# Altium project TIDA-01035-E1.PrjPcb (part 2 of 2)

## Sheet TIDA-01035_ADC1.SchDoc
size 431 x 279 mm; Date: Not shown in title block; ApprovedBy: Not shown in title block; CheckedBy: Not shown in title block; Author: Not shown in title block; CompanyName: Not shown in title block; Engineer: Not shown in title block; Organization: Not shown in title block; Address1: Not shown in title block; Address2: Not shown in title block; Address3: Not shown in title block; Address4: Not shown in title block; DocumentNumber: 1; Revision: Use project parameter SCH_Rev; SheetNumber: 5; SheetTotal: 6; PageSetup: Record=PageOptions¦CenterHorizontal=True¦CenterVertical=True¦PrintScale=0.64¦XCorrection=1.00¦YCorrection=1.00¦PrintKind=0¦BorderSize=5000000¦LeftOffset=0¦BottomOffset=0¦Orientation=2¦PaperLength=1000¦PaperWidth=1000¦Scale=100¦PaperSource=15¦PrintQuality=600¦MediaType=1¦DitherType=10¦PrintScaleMode=1¦PaperKind=Letter¦PaperIndex=1
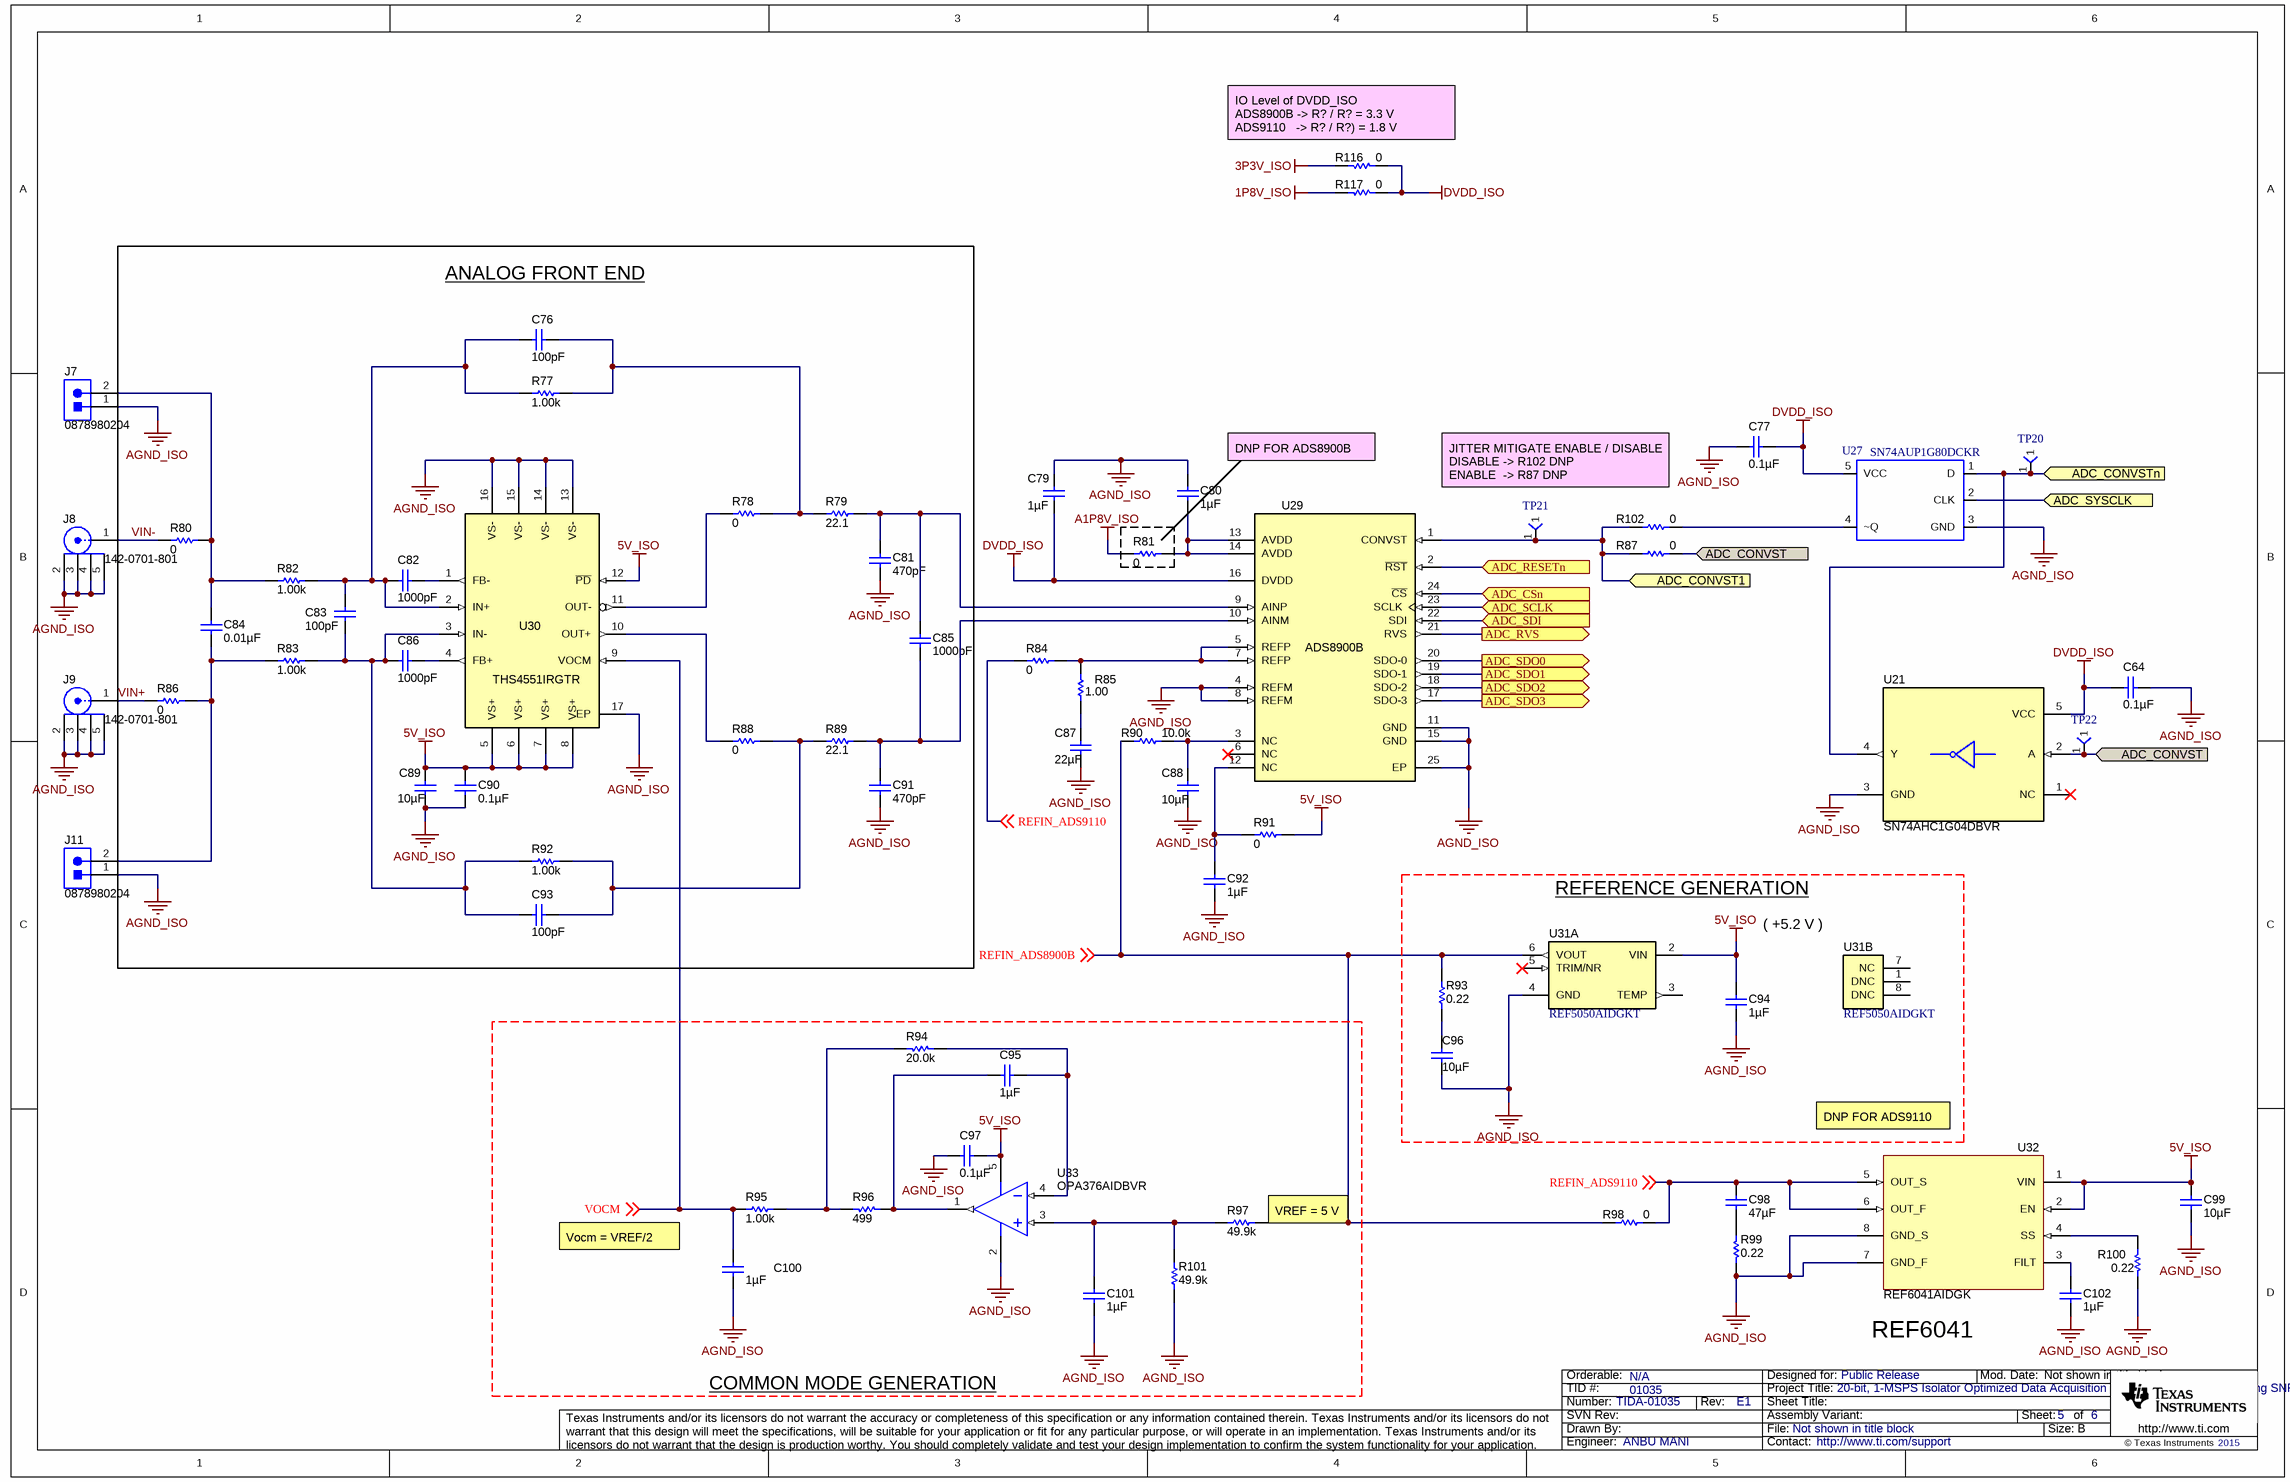
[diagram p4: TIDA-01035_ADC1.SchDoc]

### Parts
C64  ValueDisplayed: 0.1µF  [0402]  (hidden comment: GRM155R71C104KA88D)
C76  ValueDisplayed: 100pF  [0402]  (hidden comment: 885012005061)
C77  ValueDisplayed: 0.1µF  [0402]  (hidden comment: GRM155R71C104KA88D)
C79  ValueDisplayed: 1µF  [0603]  (hidden comment: GRM188R71E105KA12D)
C80  ValueDisplayed: 1µF  [0603]  (hidden comment: GRM188R71E105KA12D)
C81  ValueDisplayed: 470pF  [0805_HV]  (hidden comment: GRM2165C2A471JA01D)
C82  ValueDisplayed: 1000pF  [0603]  (hidden comment: GRM1885C1H102FA01J)
C83  ValueDisplayed: 100pF  [0402]  (hidden comment: 885012005061)
C84  ValueDisplayed: 0.01µF  [0805_HV]  (hidden comment: C0805C103F1GACTU)
C85  ValueDisplayed: 1000pF  [0805_HV]  (hidden comment: C0805C102J1GACTU)
C86  ValueDisplayed: 1000pF  [0603]  (hidden comment: GRM1885C1H102FA01J)
C87  ValueDisplayed: 22µF  [0603]  (hidden comment: GRM188R60J226MEA0J)
C88  ValueDisplayed: 10µF  [0805_HV]  (hidden comment: GRM21BR71A106KE51L)
C89  ValueDisplayed: 10µF  [0603_120]  (hidden comment: ZRB18AD71A106KE01L)
C90  ValueDisplayed: 0.1µF  [0402]  (hidden comment: GRM155R71C104KA88D)
C91  ValueDisplayed: 470pF  [0805_HV]  (hidden comment: GRM2165C2A471JA01D)
C92  ValueDisplayed: 1µF  [0603]  (hidden comment: GRM188R71E105KA12D)
C93  ValueDisplayed: 100pF  [0402]  (hidden comment: 885012005061)
C94  ValueDisplayed: 1µF  [0603]  (hidden comment: GRM188R71E105KA12D)
C95  ValueDisplayed: 1µF  [0603]  (hidden comment: GRM188R71E105KA12D)
C96  ValueDisplayed: 10µF  [0805_HV]  (hidden comment: GRM21BR71A106KE51L)
C97  ValueDisplayed: 0.1µF  [0603]  (hidden comment: C0603C104J3RACTU)
C98  ValueDisplayed: 47µF  [1210]  (hidden comment: GRM32ER71A476KE15L)
C99  ValueDisplayed: 10µF  [0805]  (hidden comment: GRM21BR71A106KE51L)
C100  ValueDisplayed: 1µF  [0603]  (hidden comment: GRM188R71E105KA12D)
C101  ValueDisplayed: 1µF  [0603]  (hidden comment: GRM188R71E105KA12D)
C102  ValueDisplayed: 1µF  [0603]  (hidden comment: GRM188R71A105KA61D)
J7  0878980204  [Molex_87898-0204]
J8  142-0701-801  [JOHNSON_142-0701-801]
J9  142-0701-801  [JOHNSON_142-0701-801]
J11  0878980204  [Molex_87898-0204]
R77  ValueDisplayed: 1.00k  [0603]  (hidden comment: RG1608P-102-B-T5)
R78  ValueDisplayed: 0  [0603]  (hidden comment: CRCW06030000Z0EA)
R79  ValueDisplayed: 22.1  [0603]  (hidden comment: RR0816Q-22R1-D-34R)
R80  ValueDisplayed: 0  [0603]  (hidden comment: ERJ-3GEY0R00V)
R81  ValueDisplayed: 0  [0402]  (hidden comment: ERJ-2GE0R00X)
R82  ValueDisplayed: 1.00k  [0603]  (hidden comment: RG1608P-102-B-T5)
R83  ValueDisplayed: 1.00k  [0603]  (hidden comment: RG1608P-102-B-T5)
R84  ValueDisplayed: 0  [0603]  (hidden comment: CRCW06030000Z0EA)
R85  ValueDisplayed: 1.00  [0603]  (hidden comment: CRCW06031R00FKEA)
R86  ValueDisplayed: 0  [0603]  (hidden comment: ERJ-3GEY0R00V)
R87  ValueDisplayed: 0  [0402]  (hidden comment: ERJ-2GE0R00X)
R88  ValueDisplayed: 0  [0603]  (hidden comment: CRCW06030000Z0EA)
R89  ValueDisplayed: 22.1  [0603]  (hidden comment: RR0816Q-22R1-D-34R)
R90  ValueDisplayed: 10.0k  [0402]  (hidden comment: ERJ-2RKF1002X)
R91  ValueDisplayed: 0  [0402]  (hidden comment: ERJ-2GE0R00X)
R92  ValueDisplayed: 1.00k  [0603]  (hidden comment: RG1608P-102-B-T5)
R93  ValueDisplayed: 0.22  [0402]  (hidden comment: ERJ-2BQFR22X)
R94  ValueDisplayed: 20.0k  [0603]  (hidden comment: RG1608P-203-B-T5)
R95  ValueDisplayed: 1.00k  [0603]  (hidden comment: CRCW06031K00FKEA)
R96  ValueDisplayed: 499  [0603]  (hidden comment: RG1608P-4990-B-T5)
R97  ValueDisplayed: 49.9k  [0603]  (hidden comment: RG1608P-4992-B-T5)
R98  ValueDisplayed: 0  [0603]  (hidden comment: CRCW06030000Z0EA)
R99  value 0.22  [0603]  (hidden comment: ERJ-3RQFR22V)
R100  value 0.22  [0603]  (hidden comment: ERJ-3RQFR22V)
R101  ValueDisplayed: 49.9k  [0603]  (hidden comment: RG1608P-4992-B-T5)
R102  ValueDisplayed: 0  [0402]  (hidden comment: ERJ-2GE0R00X)
R116  ValueDisplayed: 0  [0805_HV]  (hidden comment: CRCW08050000Z0EA)
R117  ValueDisplayed: 0  [0805_HV]  (hidden comment: CRCW08050000Z0EA)
TP20  TP-025-SMT  [TP_25MIL-SMT]  (value not drawn)
TP21  TP-025-SMT  [TP_25MIL-SMT]  (value not drawn)
TP22  TP-025-SMT  [TP_25MIL-SMT]  (value not drawn)
U21  SN74AHC1G04DBVR  [DBV0005A_N]
U27  SN74AUP1G80DCKR  [DCK0005A_N]
U29  ADS8900BIRGER  [RGE0024H]  (value not drawn)
U30  THS4551IRGTR  [RGT0016A]
U31  REF5050AIDGKT  [DGK0008A_N]  (parts A,B of 2)
U32  REF6041AIDGK  [DGK0008A_N]
U33  OPA376AIDBVR  [DBV0005A_N]

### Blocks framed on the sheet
REFERENCE GENERATION: C94 C96 R93 U31
COMMON MODE GENERATION: C95 C97 C100 C101 R94-R97 R101 U33

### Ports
ADC_CONVST1 (in), ADC_CONVST (in), ADC_CONVSTn (in), ADC_CSn (in), ADC_RESETn (in), ADC_RVS (out), ADC_SCLK (in), ADC_SDI (in), ADC_SDO0 (out), ADC_SDO1 (out), ADC_SDO2 (out), ADC_SDO3 (out), ADC_SYSCLK (in)

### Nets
1P8V_ISO: R117.2
3P3V_ISO: R116.2
5V_ISO: C89.1 C90.2 C94.1 C97.2 C99.2 R91.2 U30.5(VS+) U30.6(VS+) U30.7(VS+) U30.8(VS+) U30.12(~{PD}) U31.2(VIN) U32.1(VIN) U32.2(EN) U33.5(V+)
A1P8V_ISO: R81.1
AGND_ISO: C64.1 C77.1 C79.1 C80.2 C81.2 C87.2 C88.2 C89.2 C90.1 C91.2 C92.2 C94.2 C96.2 C97.1 C99.1 C100.2 C101.2 C102.2 J7.1 J8.2 J8.3 J8.4 J8.5 J9.2 J9.3 J9.4 J9.5 J11.1 R99.2 R100.1 R101.1 U21.3(GND) U27.3(GND) U29.4(REFM) U29.8(REFM) U29.11(GND) U29.15(GND) U29.25(EP) U30.13(VS-) U30.14(VS-) U30.15(VS-) U30.16(VS-) U30.17(EP) U31.4(GND) U32.7(GND_F) U32.8(GND_S) U33.2(V-)
DVDD_ISO: C64.2 C77.2 C79.2 R116.1 R117.1 U21.5(VCC) U27.5(VCC) U29.16(DVDD)
ADC_CONVST: R87.2 TP22.1 U21.2(A) ; port ADC_CONVST
ADC_CONVST1: R87.1 R102.1 TP21.1 U29.1(CONVST) ; port ADC_CONVST1
ADC_CONVSTn: TP20.1 U21.4(Y) U27.1(D) ; port ADC_CONVSTn
ADC_CSn: U29.24(~{CS}) ; port ADC_CSn
ADC_RESETn: U29.2(~{RST}) ; port ADC_RESETn
ADC_RVS: U29.21(RVS) ; port ADC_RVS
ADC_SCLK: U29.23(SCLK) ; port ADC_SCLK
ADC_SDI: U29.22(SDI) ; port ADC_SDI
ADC_SDO0: U29.20(SDO-0) ; port ADC_SDO0
ADC_SDO1: U29.19(SDO-1) ; port ADC_SDO1
ADC_SDO2: U29.18(SDO-2) ; port ADC_SDO2
ADC_SDO3: U29.17(SDO-3) ; port ADC_SDO3
ADC_SYSCLK: U27.2(CLK) ; port ADC_SYSCLK
REFIN_ADS8900B: R90.1 R93.2 R97.2 R98.1 U31.6(VOUT) ; off-sheet REFIN_ADS8900B
REFIN_ADS9110: C98.2 R84.2 R98.2 U32.5(OUT_S) U32.6(OUT_F) ; off-sheet REFIN_ADS9110
VIN+: J9.1 R86.1
VIN-: J8.1 R80.1
VOCM: C100.1 R95.1 U30.9(VOCM) ; off-sheet VOCM
NetC76_1: C76.1 R77.2 R78.2 R79.1
NetC76_2: C76.2 C82.2 C83.1 R77.1 R82.2 U30.2(IN+)
NetC80_1: C80.1 R81.2 U29.13(AVDD) U29.14(AVDD)
NetC81_1: C81.1 C85.1 R79.2 U29.9(AINP)
NetC82_1: C82.1 U30.1(FB-)
NetC83_2: C83.2 C86.2 C93.2 R83.2 R92.1 U30.3(IN-)
NetC84_1: C84.1 J11.2 R83.1 R86.2
NetC84_2: C84.2 J7.2 R80.2 R82.1
NetC85_2: C85.2 C91.1 R89.2 U29.10(AINM)
NetC86_1: C86.1 U30.4(FB+)
NetC87_1: C87.1 R85.1
NetC88_1: C88.1 R90.2 U29.3(NC)
NetC92_1: C92.1 R91.1 U29.12(NC)
NetC93_1: C93.1 R88.2 R89.1 R92.2
NetC95_1: C95.1 R96.1 U33.1(OUT)
NetC95_2: C95.2 R94.1 U33.4(IN-)
NetC96_1: C96.1 R93.1
NetC98_1: C98.1 R99.1
NetC101_1: C101.1 R97.1 R101.2 U33.3(IN+)
NetC102_1: C102.1 U32.3(FILT)
NetR78_1: R78.1 U30.11(OUT-)
NetR84_1: R84.1 R85.2 U29.5(REFP) U29.7(REFP)
NetR88_1: R88.1 U30.10(OUT+)
NetR94_2: R94.2 R95.2 R96.2
NetR100_2: R100.2 U32.4(SS)
NetR102_2: R102.2 U27.4(~Q)

Not connected (* = marked no-connect by the designer): U21 1(NC)*; U29 6(NC)*; U31 1(DNC) 3(TEMP) 5(TRIM/NR)* 7(NC) 8(DNC)

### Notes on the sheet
- (near R116) IO Level of DVDD_ISO
  ADS8900B -> R? / R? = 3.3 V
  ADS9110   -> R? / R?) = 1.8 V
- ANALOG FRONT END
- (near C80) DNP FOR ADS8900B
- JITTER MITIGATE ENABLE / DISABLE
  DISABLE -> R102 DNP
  ENABLE  -> R87 DNP
- (near U29) ADS8900B
- (near R93) ( +5.0 V )
- ( +5.2 V )
- DNP FOR ADS9110
- (near R97) VREF = 5 V
- Vocm = VREF/2
- REF6041

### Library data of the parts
C64 C77 C90 = GRM155R71C104KA88D: CAP, CERM, 0.1 µF, 16 V, +/- 10%, X7R, 0402; Manufacturer: MuRata; Polarized: N; CompType: Capacitor; Value: 0.1uF; U/M: EA; Cap_F: 0.0000001; Tolerance_%: 10; Value1: Unknown; VDC_V: 16; Value2: 16V; TaMin_C: -55; TaMax_C: 125
C76 C83 C93 = 885012005061: CAP, CERM, 100 pF, 50 V, +/- 5%, C0G/NP0, 0402; Manufacturer: Wurth Elektronik; Polarized: N; CompType: Capacitor; Value: 100pF; U/M: EA; Cap_F: 0.0000000001; Tolerance_%: 5; Value1: Unknown; VDC_V: 50; Value2: 50V; TaMin_C: -55; TaMax_C: 125; AEC Category: Q200
C79 C80 C94 = GRM188R71E105KA12D: CAP, CERM, 1 µF, 25 V, +/- 10%, X7R, 0603; Manufacturer: MuRata; Polarized: N; CompType: Capacitor; Value: 1uF; U/M: EA; Cap_F: 0.000001; Tolerance_%: 10; Value1: Unknown; VDC_V: 25; Value2: 25V; TaMin_C: -55; TaMax_C: 125
C81 C91 = GRM2165C2A471JA01D: CAP, CERM, 470 pF, 100 V, +/- 5%, C0G/NP0, 0805; Manufacturer: MuRata; Polarized: N; CompType: Capacitor; Value: 470pF; U/M: EA; Cap_F: 0.00000000047; Tolerance_%: 5; Value1: Unknown; VDC_V: 100; Value2: 100V; TaMin_C: -55; TaMax_C: 125; Cap_Case: 0805; SizeArea_mm2: 2.5; SizeAreaWB_mm2: 6.75; SizeX_mm: 2; SizeY_mm: 1.25; SizeZ_mm: 1.45; AEC Category: Q200
C82 C86 = GRM1885C1H102FA01J: CAP, CERM, 1000 pF, 50 V, +/- 1%, C0G/NP0, 0603; Manufacturer: MuRata; Polarized: N; CompType: Capacitor; Value: 1000pF; U/M: EA; Cap_F: 0.000000001; Tolerance_%: 1; Value1: Unknown; VDC_V: 50; Value2: 50V; TaMin_C: -55; TaMax_C: 125; AEC Category: Q200; SizeArea_mm2: 1.28; SizeAreaWB_mm2: 4.68; SizeX_mm: 1.6; SizeY_mm: 0.8
C84 = C0805C103F1GACTU: CAP, CERM, 0.01 µF, 100 V, +/- 1%, C0G/NP0, 0805; Manufacturer: Kemet; Polarized: N; CompType: Capacitor; Value: 0.01uF; U/M: EA; Cap_F: 0.00000001; Tolerance_%: 1; Value1: Unknown; VDC_V: 100; Value2: 100V; TaMin_C: -55; TaMax_C: 125; Cap_Case: 0805; AEC Category: Q200
C85 = C0805C102J1GACTU: CAP, CERM, 1000 pF, 100 V, +/- 5%, C0G/NP0, 0805; Manufacturer: Kemet; Polarized: N; CompType: Capacitor; Value: 1000pF; U/M: EA; Cap_F: 0.000000001; Tolerance_%: 5; ESR_ohm: 0.025; Value1: 0.025 ohm; VDC_V: 100; Value2: 100V; IRMS_A: 1.71; TaMin_C: -55; TaMax_C: 125; Cap_Case: 0805; SizeArea_mm2: 2.5; SizeAreaWB_mm2: 6.75; SizeX_mm: 2; SizeY_mm: 1.25; SizeZ_mm: 1.45; AEC Category: Q200
C87 = GRM188R60J226MEA0J: CAP, CERM, 22 µF, 6.3 V, +/- 20%, X5R, 0603; Manufacturer: MuRata; Polarized: N; CompType: Capacitor; Value: 22uF; U/M: EA; Cap_F: 0.000022; Tolerance_%: 20; Value1: Unknown; VDC_V: 6.3; Value2: 6.3V; TaMin_C: -55; TaMax_C: 85; AEC Category: Q200
C88 C96 = GRM21BR71A106KE51L: CAP, CERM, 10 µF, 10 V, +/- 10%, X7R, 0805; Manufacturer: MuRata; Polarized: N; CompType: Capacitor; Value: 10uF; U/M: EA; Cap_F: 0.00001; Tolerance_%: 10; ESR_ohm: 0.003; Value1: 0.003 ohm; Value2: 10V; TaMin_C: -55; TaMax_C: 125; Cap_Case: 0805; AEC Category: Q200
C89 = ZRB18AD71A106KE01L: CAP, CERM, 10 µF, 10 V, +/- 10%, X7T, 0603; Manufacturer: MuRata; Polarized: N; CompType: Capacitor; Value: 10uF; U/M: EA; Cap_F: 0.00001; Tolerance_%: 10; Value1: Unknown; Value2: 10V; TaMin_C: -55; TaMax_C: 125; Cap_Case: 0603; AEC Category: Q200
C92 C95 C100 C101 = GRM188R71E105KA12D: CAP, CERM, 1 µF, 25 V, +/- 10%, X7R, 0603; Manufacturer: MuRata; Polarized: N; CompType: Capacitor; Value: 1uF; U/M: EA; Cap_F: 0.000001; Tolerance_%: 10; Value1: Unknown; VDC_V: 25; Value2: 25V; TaMin_C: -55; TaMax_C: 125; AEC Category: Q200
C97 = C0603C104J3RACTU: CAP, CERM, 0.1 µF, 25 V, +/- 5%, X7R, 0603; Manufacturer: Kemet; Polarized: N; CompType: Capacitor; Value: 0.1uF; U/M: EA; Cap_F: 0.0000001; Tolerance_%: 5; Value1: Unknown; VDC_V: 25; Value2: 25V; TaMin_C: -55; TaMax_C: 125; AEC Category: Q200
C98 = GRM32ER71A476KE15L: CAP, CERM, 47 µF, 10 V, +/- 10%, X7R, 1210; Manufacturer: MuRata; Polarized: N; CompType: Capacitor; Value: 47uF; U/M: EA; Cap_F: 0.000047; Tolerance_%: 10; Value1: Unknown; Value2: 10V; TaMin_C: -55; TaMax_C: 125
C99 = GRM21BR71A106KE51L: CAP, CERM, 10uF, 10V, +/-10%, X7R, 0805; Manufacturer: MuRata; Polarized: N; CompType: Capacitor; U/M: EA; Cap_F: 0.00001; Tolerance_%: 10; ESR_Ohm: 0.003; Value1: 0.003 ohm; TaMin_C: -55; TaMax_C: 125
C102 = GRM188R71A105KA61D: CAP, CERM, 1uF, 10V, +/-10%, X7R, 0603; Manufacturer: MuRata; Polarized: N; CompType: Capacitor; U/M: EA; Cap_F: 0.000001; Tolerance_%: 10; ESR_Ohm: 0.011; Value1: 0.011 ohm; TaMin_C: -55; TaMax_C: 125
J7 J11 = 87898-0204: Header, 2.54 mm, 2x1, Gold, R/A, SMT; Manufacturer: Molex; SymbolCreator: a0412235; U/M: EA
J8 J9 = 142-0701-801: Connector, End launch SMA, 50 ohm, SMT; Manufacturer: Johnson; SymbolCreator: X0208326; U/M: EA
R77 R82 R83 R92 = RG1608P-102-B-T5: RES, 1.00 k, 0.1%, 0.1 W, 0603; Manufacturer: Susumu Co Ltd; CompType: Resistor; Value: 1.00k; Res_ohm: 1000; Value_Code: 1k00; Tolerance_%: 0.1; Value2: 0.1W; VDC_V: 75; TempCo: 25 ppm/C; EIA_Code: E192; U/M: EA
R78 R88 = CRCW06030000Z0EA: RES, 0, 5%, 0.1 W, 0603; Manufacturer: Vishay-Dale; CompType: Resistor; Value: 0; Value_Code: 0000; Tolerance_%: 5; Power_W: 0.1; Value2: 0.1W; VDC_V: 75; TempCo: 200 ppm/C; EIA_Code: E24; U/M: EA; AEC Category: Q200; SizeArea_mm2: 1.28; SizeX_mm: 1.6; SizeY_mm: 0.8; SizeZ_mm: 1
R79 R89 = RT0603BRD0722R1L: RES SMD 22.1 OHM 0.5% 1/16W 0603; Manufacturer: Susumu; CompType: Resistor; Value: 22.1; Value_Code: 22R1; Tolerance_%: 0.1; Value1: 0.1%; Value2: 0.1W; VDC_V: 75; TempCo: 25 ppm/C; EIA_Code: E192; U/M: EA; SizeArea_mm2: 1.28; SizeX_mm: 1.6; SizeY_mm: 0.8; SizeZ_mm: 1; AEC Category: Q200
R80 R86 = ERJ-3GEY0R00V: RES, 0, 5%, 0.1 W, 0603; Manufacturer: Panasonic; CompType: Resistor; Value: 0; Value_Code: 0000; Tolerance_%: 5; Power_W: 0.1; Value2: 0.1W; VDC_V: 50; TempCo: 600 ppm/C; EIA_Code: E24; U/M: EA; AEC Category: Q200
R81 R87 R91 R102 = ERJ-2GE0R00X: RES, 0, 5%, 0.063 W, 0402; Manufacturer: Panasonic; CompType: Resistor; Value: 0; Value_Code: 0000; Tolerance_%: 5; Power_W: 0.063; Value2: 0.063W; VDC_V: 50; TempCo: 600 ppm/C; EIA_Code: E24; U/M: EA; AEC Category: Q200
R84 R98 = CRCW06030000Z0EA: RES, 0, 5%, 0.1 W, 0603; Manufacturer: Vishay-Dale; CompType: Resistor; Value: 0; Value_Code: 0000; Tolerance_%: 5; Power_W: 0.1; Value2: 0.1W; VDC_V: 75; TempCo: 200 ppm/C; EIA_Code: E24; U/M: EA; AEC Category: Q200
R85 = CRCW06031R00FKEA: RES, 1.00, 1%, 0.1 W, 0603; Manufacturer: Vishay-Dale; CompType: Resistor; Value: 1.00; Res_ohm: 1; Value_Code: 1R00; Power_W: 0.1; Value2: 0.1W; VDC_V: 75; TempCo: 100 ppm/C; EIA_Code: E96; U/M: EA; AEC Category: Q200
R90 = ERJ-2RKF1002X: RES, 10.0 k, 1%, 0.1 W, 0402; Manufacturer: Panasonic; CompType: Resistor; Value: 10.0k; Res_ohm: 10000; Value_Code: 10k0; Tolerance_%: 1; Power_W: 0.1; Value2: 0.1W; VDC_V: 50; TempCo: 100 ppm/C; EIA_Code: E96; U/M: EA; AEC Category: Q200
R93 = ERJ-2BQFR22X: RES, 0.22, 1%, 0.125 W, 0402; Manufacturer: Panasonic; CompType: Resistor; Value: 0.22; Value_Code: R220; Tolerance_%: 1; Power_W: 0.125; Value2: 0.125W; TempCo: 250 ppm/C; EIA_Code: E96; U/M: EA; AEC Category: Q200
R94 = RG1608P-203-B-T5: RES, 20.0 k, 0.1%, 0.1 W, 0603; Manufacturer: Susumu Co Ltd; CompType: Resistor; Value: 20.0k; Res_ohm: 20000; Value_Code: 20k0; Tolerance_%: 0.1; Value2: 0.1W; VDC_V: 75; TempCo: 25 ppm/C; EIA_Code: E192; U/M: EA; AEC Category: Q200
R95 = CRCW06031K00FKEA: RES, 1.00 k, 1%, 0.1 W, 0603; Manufacturer: Vishay-Dale; CompType: Resistor; Value: 1.00k; Res_ohm: 1000; Value_Code: 1k00; Tolerance_%: 1; Power_W: 0.1; Value2: 0.1W; VDC_V: 75; TempCo: 100 ppm/C; EIA_Code: E96; U/M: EA; AEC Category: Q200
R96 = RG1608P-4990-B-T5: RES, 499, 0.1%, 0.1 W, 0603; Manufacturer: Susumu Co Ltd; CompType: Resistor; Value: 499; Value_Code: 499R; Tolerance_%: 0.1; Value2: 0.1W; VDC_V: 75; TempCo: 25 ppm/C; EIA_Code: E192; U/M: EA; AEC Category: Q200
R97 R101 = RG1608P-4992-B-T5: RES, 49.9 k, 0.1%, 0.1 W, 0603; Manufacturer: Susumu Co Ltd; CompType: Resistor; Value: 49.9k; Res_ohm: 49900; Value_Code: 49k9; Tolerance_%: 0.1; Value2: 0.1W; VDC_V: 75; TempCo: 25 ppm/C; EIA_Code: E192; U/M: EA; AEC Category: Q200
R99 R100 = ERJ-3RQFR22V: RES, 0.22 ohm, 1%, 0.1W, 0603; Manufacturer: Panasonic; CompType: Resistor; Value_Code: R220; Tolerance_%: 1; Power_W: 0.1; TempCo: 300 ppm/C; EIA_Code: E96; U/M: EA
R116 R117 = CRCW08050000Z0EA: RES, 0, 5%, 0.125 W, 0805; Manufacturer: Vishay-Dale; CompType: Resistor; Value: 0; Value_Code: 0000; Tolerance_%: 5; Power_W: 0.125; Value2: 0.125W; VDC_V: 150; TempCo: 200 ppm/C; EIA_Code: E24; U/M: EA; AEC Category: Q200
TP20-TP22 = TP-025-SMT: Test Point, O.025"; Manufacturer: STD; Value: STD
U21 = SN74AHC1G04DBVR: SINGLE SCHMITT-TRIGGER INVERTER GATE, DBV0005A; Alternate PartNumber: SN74AHC1G04DBVT; Manufacturer: Texas Instruments; SymbolCreator: a0411947; CompType: IC; U/M: EA
U27 = SN74AUP1G80DCK: IC, Single Positive-Edge-Triggered D-Type Flip-Flop; Manufacturer: TI; Alternate Manufacturer: None; Area: 23200
U29 = ADS9110IRGER: 18-Bit, 2-MSPS, 20-mW, SAR ADC with Enhanced Serial Interface, RGE0024H; Alternate PartNumber: ADS9110IRGET; Manufacturer: Texas Instruments; SymbolCreator: Altium; CompType: IC; U/M: EA
U30 = THS4551IRGTR: Low Power, Precision, 160MHz, Fully Differential Amplifier, RGT0016A; Alternate PartNumber: THS4551IRGTT; Manufacturer: Texas Instruments; SymbolCreator: Altium; SizeX_mm: 4; SizeZ_mm: 1; CompType: IC; U/M: EA
U31 = REF5050AIDGKT: Low Noise, Very Low Drift, Precision Voltage Reference, -40 to 125 degC, 8-pin VSSOP (DGK), Green (RoHS & no Sb/Br); Manufacturer: Texas Instruments; Alternate PartNumber: Equivalent; Initial Accuracy @ 25/deg C(%): 0.05; Iout/Iz(Max)(mA): 10; Iq(Max)(uA): 1000; Rating: Catalog; SubFamily: Series Voltage Reference; Temp Coeff(Max)(ppm/ degree C): 3; VI(Max)(V): 18; VI(Min)(V): 5.2; VO(V): 5
U32 = REF6025AIDGK: High-Precision Voltage Reference with Integrated High-Bandwidth Buffer, DGK0008A; Manufacturer: Texas Instruments; SymbolCreator: Altium; CompType: IC; U/M: EA
U33 = OPA376AIDBVR: Precision, Low Noise, Low Iq Operational Amplifier, 2.2 to 5.5 V, -40 to 125 degC, 5-pin SOT23 (DBV0005A), Green (RoHS & no Sb/Br); Manufacturer: Texas Instruments; Alternate PartNumber: Equivalent; CMRR(Min)(dB): 76; IIB(Max)(pA): 10; Iq per channel(Max)(mA): 0.95; Number of Channels: 1; Offset Drift(Typ)(uV/C): 0.32; Slew Rate(Typ)(V/us): 2; Sub Family: Low Input Bias Current Amp (<=10pA), Low Noise Amp (<=10nV/rtHz), Low Offset Voltage Amplifier (<=500uV), Low Supply Voltage Amplifier (<=2.7V), Precision Amplifier; Total Supply Voltage(Max)(+5V is 5, +/-5V is 10): 5.5; Total Supply Voltage(Min)(+5V is 5, +/-5V is 10): 2.2; Vio (25C)(Max)(mV): 0.025; Vn at 1kHz(Typ)(nV/rtHz): 7.5

## Sheet TIDA-01035_Hardware.SchDoc
size 431 x 279 mm; Date: Not shown in title block; ApprovedBy: Not shown in title block; CheckedBy: Not shown in title block; Author: Not shown in title block; CompanyName: Not shown in title block; Engineer: Not shown in title block; Organization: Not shown in title block; Address1: Not shown in title block; Address2: Not shown in title block; Address3: Not shown in title block; Address4: Not shown in title block; DocumentNumber: 1; Revision: Use project parameter SCH_Rev; SheetNumber: 6; SheetTotal: 6; PageSetup: Record=PageOptions¦CenterHorizontal=True¦CenterVertical=True¦PrintScale=1.00¦XCorrection=1.00¦YCorrection=1.00¦PrintKind=0¦BorderSize=5000000¦LeftOffset=0¦BottomOffset=0¦Orientation=2¦PaperLength=1000¦PaperWidth=1000¦Scale=100¦PaperSource=15¦PrintQuality=600¦MediaType=1¦DitherType=10¦PaperKind=Letter¦PrintScaleMode=1
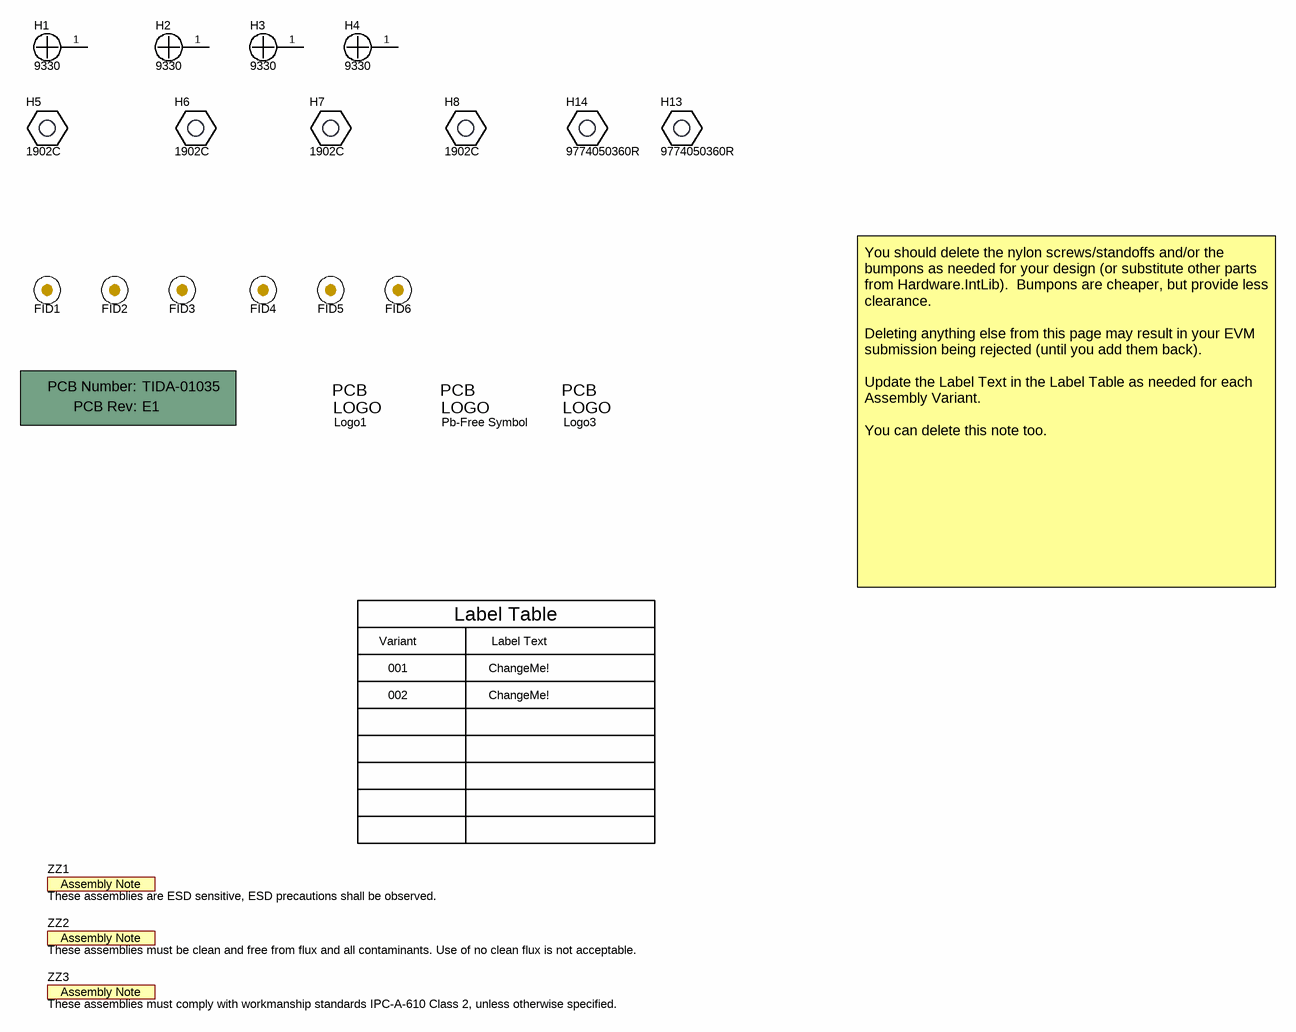
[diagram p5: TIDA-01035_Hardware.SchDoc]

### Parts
!PCB1  Printed Circuit Board  (value not drawn)  (mechanical)
FID1  Fiducial  [Fiducial10-20]  (value not drawn)
FID2  Fiducial  [Fiducial10-20]  (value not drawn)
FID3  Fiducial  [Fiducial10-20]  (value not drawn)
FID4  Fiducial  [Fiducial10-20]  (value not drawn)
FID5  Fiducial  [Fiducial10-20]  (value not drawn)
FID6  Fiducial  [Fiducial10-20]  (value not drawn)
H1  9330  [NY PMS 440 0025 PH]
H2  9330  [NY PMS 440 0025 PH]
H3  9330  [NY PMS 440 0025 PH]
H4  9330  [NY PMS 440 0025 PH]
H5  1902C  [Keystone_1902C]
H6  1902C  [Keystone_1902C]
H7  1902C  [Keystone_1902C]
H8  1902C  [Keystone_1902C]
H13  9774050360R  [Wurth_WA-SMSI]
H14  9774050360R  [Wurth_WA-SMSI]
Logo1  ESD Susceptible  [ESD_Overlay_small]  (value not drawn)  (no BOM)
Logo2  Pb-Free Symbol  [Pb-Free_Overlay_Small]  (no BOM)
Logo3  FCC disclaimer  [FCC_disclaimer]  (value not drawn)  (no BOM)
ZZ1  These assemblies are ESD sensitive, ESD precautions shall be observed.  [AssemblyNote]  (no BOM)
ZZ2  These assemblies must be clean and free from flux and all contaminants. Use of no clean flux is not acceptable.  [AssemblyNote]  (no BOM)
ZZ3  These assemblies must comply with workmanship standards IPC-A-610 Class 2, unless otherwise specified.  [AssemblyNote]  (no BOM)

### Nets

Not connected (* = marked no-connect by the designer): H1 1; H2 1; H3 1; H4 1

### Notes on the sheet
- Variant
- Label Table
- Label Text
- You should delete the nylon screws/standoffs and/or the bumpons as needed for your design (or substitute other parts from Hardware.IntLib).  Bumpons are cheaper, but provide less clearance.
  Deleting anything else from this page may result in your EVM submission being rejected (until you add them back).
  Update the Label Text in the Label Table as needed for each Assembly Variant.
  You can delete this note too.
- 001
- 002
- ChangeMe!

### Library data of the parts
!PCB1 = PCB: Manufacturer: Any; PartNumber: TIDA-01035; SymbolCreator: a0412235
FID1-FID6 = Fiducial: Fiducial mark.  There is nothing to buy or mount.; SymbolCreator: codlsc
H1-H4 = NY PMS 440 0025 PH: Machine Screw, Round, #4-40 x 1/4, Nylon, Philips panhead; Manufacturer: Keystone Electronics; CompType: Hardware; SymbolCreator: codlsc; U/M: EA
H5-H8 = 1902C: Standoff, Hex, 0.5"L #4-40 Nylon; Manufacturer: Keystone; CompType: Hardware
H13 H14 = 9774050360R: ROUND STANDOFF M3 STEEL 11MM; Manufacturer: Wurth Elektronik; SymbolCreator: a0412235
Logo1 = ESD_Susceptible: ESD Susceptible Symbol; SymbolCreator: a0412235
Logo2 = Pb-Free: SymbolCreator: a0412235
Logo3 = FCC_disclaimer: SymbolCreator: a0412235
ZZ1-ZZ3 = AssemblyNote: SymbolCreator: codlsc

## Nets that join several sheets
1P8V_ISO: TIDA-01035_CONNECTOR (C11.1 U3.5), TIDA-01035_POWER_ISOLATION (C38.1 C39.1 TP8.1 U9.5), TIDA-01035_ADC1 (R117.2)
3P3V: TIDA-01035_POWER_ISOLATION (5 pins), TIDA-01035_DATA_ISOLATION (12 pins)
3P3V_ISO: TIDA-01035_CONNECTOR (7 pins), TIDA-01035_POWER_ISOLATION (5 pins), TIDA-01035_DATA_ISOLATION (22 pins), TIDA-01035_ADC1 (R116.2)
5V_ISO: TIDA-01035_POWER_ISOLATION (5 pins), TIDA-01035_ADC1 (15 pins)
A1P8V_ISO: TIDA-01035_POWER_ISOLATION (C42.1 C43.1 TP9.1 U10.5), TIDA-01035_ADC1 (R81.1)
AGND_ISO: TIDA-01035_CONNECTOR (11 pins), TIDA-01035_POWER_ISOLATION (45 pins), TIDA-01035_DATA_ISOLATION (37 pins), TIDA-01035_ADC1 (47 pins)
DVDD_ISO: TIDA-01035_CONNECTOR (5 pins), TIDA-01035_DATA_ISOLATION (7 pins), TIDA-01035_ADC1 (8 pins)
GND: TIDA-01035_CONNECTOR (14 pins), TIDA-01035_POWER_ISOLATION (27 pins), TIDA-01035_DATA_ISOLATION (15 pins)
ADC_CONVST: TIDA-01035_DATA_ISOLATION (R62.2 U12.11), TIDA-01035_ADC1 (R87.2 TP22.1 U21.2)
ADC_CSn: TIDA-01035_DATA_ISOLATION (R68.2 U12.12), TIDA-01035_ADC1 (U29.24)
ADC_RESETn: TIDA-01035_DATA_ISOLATION (R57.2 U12.10), TIDA-01035_ADC1 (U29.2)
ADC_RVS: TIDA-01035_DATA_ISOLATION (R76.2 U13.11), TIDA-01035_ADC1 (U29.21)
ADC_SCLK: TIDA-01035_DATA_ISOLATION (R60.2 U12.13), TIDA-01035_ADC1 (U29.23)
ADC_SDI: TIDA-01035_DATA_ISOLATION (R67.2 U13.13), TIDA-01035_ADC1 (U29.22)
ADC_SDO0: TIDA-01035_DATA_ISOLATION (R66.2 U14.10), TIDA-01035_ADC1 (U29.20)
ADC_SDO1: TIDA-01035_DATA_ISOLATION (R58.2 U14.11), TIDA-01035_ADC1 (U29.19)
ADC_SDO2: TIDA-01035_DATA_ISOLATION (R61.2 U14.12), TIDA-01035_ADC1 (U29.18)
ADC_SDO3: TIDA-01035_DATA_ISOLATION (R63.2 U14.13), TIDA-01035_ADC1 (U29.17)
ADC_SYSCLK: TIDA-01035_CONNECTOR (R14.2 R17.2 TP1.1), TIDA-01035_DATA_ISOLATION (R71.2 U13.10), TIDA-01035_ADC1 (U27.2)
CONVST: TIDA-01035_CONNECTOR (R3.1), TIDA-01035_DATA_ISOLATION (U11.5)
CSn: TIDA-01035_CONNECTOR (R4.1), TIDA-01035_DATA_ISOLATION (U11.4)
ISO_SCL: TIDA-01035_CONNECTOR (J3.3 R16.1 U2.8), TIDA-01035_DATA_ISOLATION (R73.1 U25.6)
ISO_SDA: TIDA-01035_CONNECTOR (J3.2 R15.1 U2.7), TIDA-01035_DATA_ISOLATION (R75.1 U25.7)
NISO_SCL: TIDA-01035_CONNECTOR (J1.58 U1.6), TIDA-01035_DATA_ISOLATION (R74.1 U25.3)
NISO_SDA: TIDA-01035_CONNECTOR (J1.56 U1.5), TIDA-01035_DATA_ISOLATION (R72.1 U25.2)
RVS: TIDA-01035_CONNECTOR (R8.1), TIDA-01035_DATA_ISOLATION (U19.5)
SCLK: TIDA-01035_CONNECTOR (R5.1), TIDA-01035_DATA_ISOLATION (U11.3)
SDI: TIDA-01035_CONNECTOR (R2.1), TIDA-01035_DATA_ISOLATION (U19.4)
SDO0: TIDA-01035_CONNECTOR (R9.1), TIDA-01035_DATA_ISOLATION (U22.14)
SDO1: TIDA-01035_CONNECTOR (R10.1), TIDA-01035_DATA_ISOLATION (U22.13)
SDO2: TIDA-01035_CONNECTOR (R11.1), TIDA-01035_DATA_ISOLATION (U22.12)
SDO3: TIDA-01035_CONNECTOR (R12.1), TIDA-01035_DATA_ISOLATION (U22.11)
SRESETn: TIDA-01035_CONNECTOR (R1.1), TIDA-01035_DATA_ISOLATION (U11.6)
SYSCLK: TIDA-01035_CONNECTOR (R7.1), TIDA-01035_DATA_ISOLATION (U19.6)

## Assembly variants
ADS8900B: not fitted C6 C40 C41 C42 C43 C46 C47 C48 C49 C50 C51 C76 C83 C84 C93 C98 C99 C102 FID1 FID2 FID3 R13 R14 R18 R27 R28 R30 R32 R37 R41 R42 R43 R44 R45 R46 R49 R50 R51 R52 R81 R84 R87 R98 R99 R100 R103 R105 R106 R107 R108 R109 R110 R111 R112 R113 R114 R115 R117 T2 U10 U12 U13 U14 U32 Y1
ADS9110: not fitted C6 C76 C81 C83 C84 C88 C91 C92 C93 C96 FID1 FID2 FID3 R13 R17 R27 R28 R30 R32 R37 R41 R42 R43 R44 R45 R46 R49 R50 R51 R52 R57 R58 R60 R61 R62 R63 R66 R67 R68 R71 R76 R87 R90 R91 R93 R103 T2 U31 Y1
ADS8900B_Proto: not fitted C6 C76 C81 C83 C84 C91 C93 FID1 FID2 FID3 R13 R14 R27 R28 R30 R32 R37 R41 R42 R43 R44 R45 R46 R49 R50 R51 R52 R57 R58 R60 R61 R62 R63 R66 R67 R68 R71 R76 R81 R84 R87 R98 R103 R117 T2 Y1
